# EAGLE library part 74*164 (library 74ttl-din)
8-bit parallel out SHIFT REGISTER
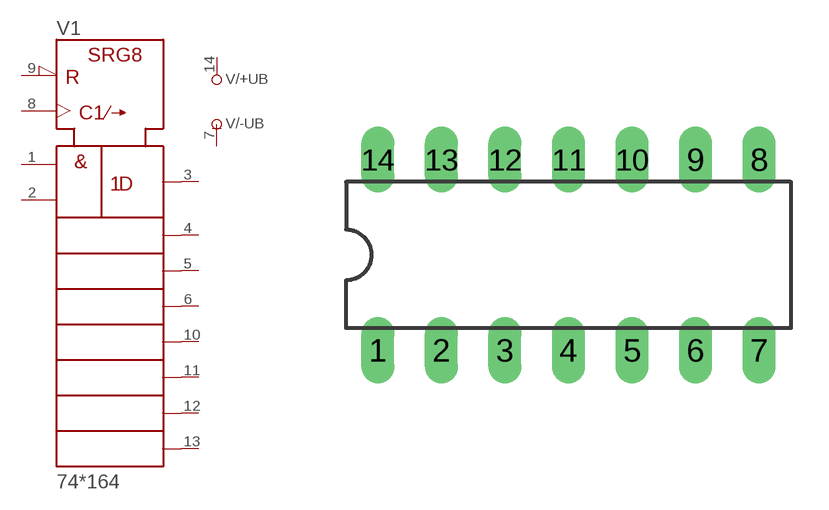
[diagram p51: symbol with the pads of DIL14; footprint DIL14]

Designator prefix V; gates /+UB=+UB /-UB=-UB 1=164

## 74164N  [DIL14]
1  1:A  in
2  1:B  in
3  1:QA  out
4  1:QB  out
5  1:QC  out
6  1:QD  out
7  /-UB:-UB  pwr
8  1:CLK  in
9  1:CLR\  in
10  1:QE  out
11  1:QF  out
12  1:QG  out
13  1:QH  out
14  /+UB:+UB  pwr

## Footprint DIL14 (pad centres in mm)
Dual In Line Package
drill 0.813 long: 1 -7.62,-3.81; 2 -5.08,-3.81; 3 -2.54,-3.81; 4 0,-3.81; 5 2.54,-3.81; 6 5.08,-3.81; 7 7.62,-3.81; 8 7.62,3.81; 9 5.08,3.81; 10 2.54,3.81; 11 0,3.81; 12 -2.54,3.81; 13 -5.08,3.81; 14 -7.62,3.81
